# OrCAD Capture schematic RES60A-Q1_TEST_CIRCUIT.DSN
size A; title: RES60A-Q1 Automotive, 1400-VDC, Precision Resistor Divider; rev: 1.0; note: Datasheet: SLPS764 - AUGUST 2024
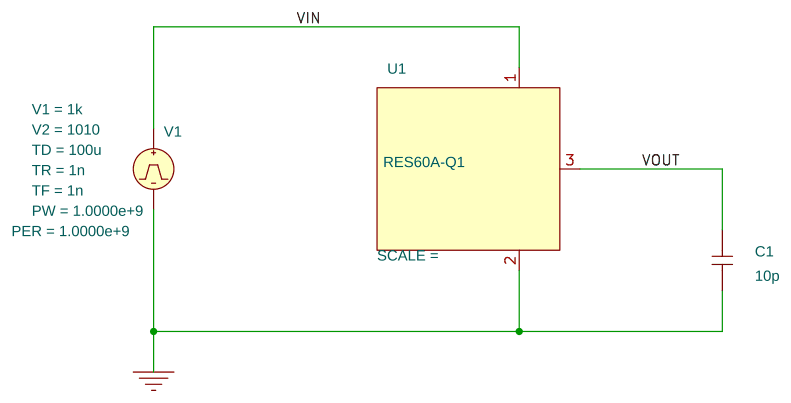
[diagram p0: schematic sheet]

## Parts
C1  10p  [cap196]
U1  RES60A-Q1
V1  VPULSE

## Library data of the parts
C1 = C
U1 = RES60A-Q1
V1 = VPULSE: AC: 1; AppProp: Pulse$Voltage$0$-1; DC: 1.4k; PER: 1.0000e+9; PW: 1.0000e+9; TD: 100u; TF: 1n; TR: 1n; V1: 1k; V2: 1010

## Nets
VIN: U1.1(HVIN) V1.1(+)
0: C1.1 U1.2(LVIN) V1.2(-)
VOUT: C1.2 U1.3(MID)
